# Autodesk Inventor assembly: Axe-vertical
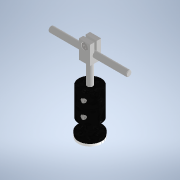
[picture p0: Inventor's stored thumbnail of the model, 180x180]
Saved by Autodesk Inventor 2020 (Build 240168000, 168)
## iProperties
Created: 2023-10
Part Number: Axe-vertical
Document SubType Name: Assembly
Designer: bruno
Author: bruno
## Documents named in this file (8)
- C:\Users\bruno\Documents\1-Cours-2023-24\Maquettes-Inventor\Pince-robot-Dobot\Axe-vertical.iam
- C:\Users\bruno\Documents\1-Cours-2023-24\Maquettes-Inventor\Pince-robot-Dobot\Palonier.iam
- C:\Users\bruno\Documents\1-Cours-2023-24\Maquettes-Inventor\Pince-robot-Dobot\Axe-servo.ipt
- C:\Users\bruno\Documents\1-Cours-2023-24\Maquettes-Inventor\Pince-robot-Dobot\Hub.ipt
- C:\Users\bruno\Documents\1-Cours-2023-24\Maquettes-Inventor\Pince-robot-Dobot\Axe-vertical.ipt
- C:\Users\bruno\Documents\1-Cours-2023-24\Maquettes-Inventor\Pince-robot-Dobot\axe-lateral.ipt
- C:\Users\bruno\Documents\Inventor\Content Center Files\R2020\fr-FR\KS B 1003\KS B 1003 - M 3 x 5.ipt
- C:\Users\bruno\Documents\Inventor\Content Center Files\R2020\fr-FR\KS B 1003\KS B 1003 - M 2 x 5.ipt
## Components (8 placed, 7 different names)
1. Palonier:1 [sub-assembly]
2. Axe-servo:1 — Placage:1, Affleurement:1
3. Hub:1 — Placage:1, Affleurement:1, Placage:2, Affleurement:2, Logement:2, Logement:3
4. Axe-vertical:1 — Placage:2, Affleurement:2, Placage:3, Affleurement:3, Logement:1
5. axe-lateral:1 — Placage:3, Affleurement:3
6. KS B 1003 - Métrique M 3 x 5:1 — Logement:1
7. KS B 1003 - Métrique M 2 x 5:1 — Logement:2
8. KS B 1003 - Métrique M 2 x 5:2 — Logement:3
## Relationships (9: Mate 3, Flush 3, Insert 3)
- Placage:1 [Mate]: Axe-servo:1 ↔ Hub:1
- Affleurement:1 [Flush]: Axe-servo:1 ↔ Hub:1
- Placage:2 [Mate]: Hub:1 ↔ Axe-vertical:1
- Affleurement:2 [Flush]: Hub:1 ↔ Axe-vertical:1
- Placage:3 [Mate]: Axe-vertical:1 ↔ axe-lateral:1
- Affleurement:3 [Flush]: Axe-vertical:1 ↔ axe-lateral:1
- Logement:1 [Insert]: Axe-vertical:1 ↔ KS B 1003 - Métrique M 3 x 5:1
- Logement:2 [Insert]: Hub:1 ↔ KS B 1003 - Métrique M 2 x 5:1
- Logement:3 [Insert]: Hub:1 ↔ KS B 1003 - Métrique M 2 x 5:2
